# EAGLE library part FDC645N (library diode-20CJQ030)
Fairchild's FDC645N N-Channel PowerTrench MOSFET Description: This N-Channel MOSFET has been designed specifically to improve the overall efficiency of DC/DC converters using either synchronous or conventional switching PWM controllers. It has been optimized for low gate charge, low RDS(ON) and fast switching speed. Features: 5.5 A, 30 V. RDS(ON) = 30mOhm @ VGS = 4.5 V RDS(ON) = 26mOhm @ VGS = 10 V High performance trench technology for extremely low RDS(ON). Low gate charge (13 nC typical) High power and current handling capability Applications: DC/DC converter Please send any comments to: messi@users.sourceforge.net
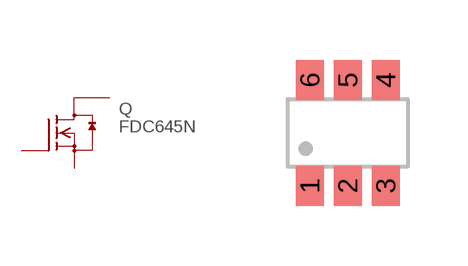
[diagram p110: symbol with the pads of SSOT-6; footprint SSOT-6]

Designator prefix Q

## FDC645N  [SSOT-6]
1  D  pas
2  D  pas
3  G  pas
4  S  pas
5  D  pas
6  D  pas

## Footprint SSOT-6 (pad centres in mm)
SuperSOT-6 (FS PKG Code 31, 33) E.g.: FDC6305N Dual N-Channel 2.5V Specified PowerTrench MOSFET
smd 0.7 x 1: 1 -0.95,-1.325; 2 0,-1.325; 3 0.95,-1.325; 4 0.95,1.325; 5 0,1.325; 6 -0.95,1.325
